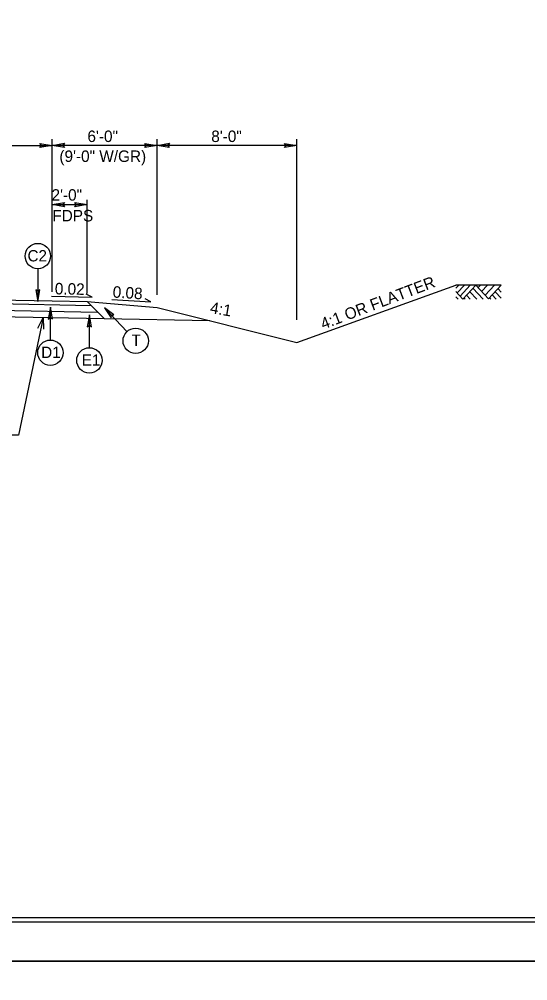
# Model space of a CAD drawing. Extents: x 1901670 to 1902225, y 193498 to 194278.
# Drawn here: x 1902035.7 to 1902064.8, y 193606.9 to 193661.9 of the extents above; entities that cross this region are included whole.
import ezdxf

# ---------------------------------------------------------------- set-up
doc = ezdxf.new("R2010")
doc.units = 0
for name, color, linetype in [('Old_Level_1', 7, 'Continuous'), ('Old_Level_11', 7, 'Continuous'), ('Old_Level_2', 7, 'Continuous'), ('Old_Level_20', 7, 'Continuous'), ('Prop Dimension', 7, 'Continuous'), ('Prop Dimension Text', 7, 'Continuous'), ('Sheet Border Standard 30in CELL', 7, 'Continuous'), ('Sheet Cutting Line CELL', 7, 'Continuous'), ('Sheet Plot Border Inside CELL', 7, 'Continuous'), ('Sheet Plot Border Outside CELL', 7, 'Continuous'), ('Typical Hinge Slope Interstate CELL', 7, 'Continuous'), ('Typical Pavement Slope CELL', 7, 'Continuous'), ('Typical Terminator CELL', 7, 'Continuous')]:
    doc.layers.add(name, color=color, linetype=linetype)

# ---------------------------------------------------------------- blocks, each defined once
blk = doc.blocks.new('TERMINATOR')
at = {"layer": 'Typical Terminator CELL'}
blk.add_lwpolyline([(-0.469, 0.081), (0, 0), (-0.471, -0.083), (-0.411, 0)], close=True, dxfattribs=at)

msp = doc.modelspace()

# ---------------------------------------------------------------- linework, layer by layer
at = {"layer": 'Old_Level_1'}
for p, q in [((1902043.616, 193646.129), (1902043.616, 193655.04)), ((1902060.879, 193646.683), (1902060.709, 193646.5)), ((1902061.113, 193645.886), (1902060.709, 193646.321)), ((1902061.199, 193646.683), (1902060.785, 193646.239)), ((1902061.532, 193646.683), (1902060.952, 193646.06)), ((1902061.854, 193646.682), (1902061.113, 193645.886)), ((1902061.905, 193645.878), (1902061.505, 193646.307)), ((1902062.275, 193645.878), (1902061.689, 193646.506)), ((1902062.586, 193645.896), (1902061.854, 193646.682)), ((1902062.118, 193646.683), (1902061.985, 193646.54)), ((1902062.52, 193646.683), (1902062.187, 193646.324)), ((1902062.918, 193646.683), (1902062.385, 193646.11)), ((1902063.309, 193646.675), (1902062.586, 193645.896)), ((1902063.309, 193645.941), (1902062.967, 193646.307)), ((1902063.309, 193646.274), (1902063.124, 193646.474)), ((1902025.621, 193646.02), (1902037.616, 193645.78)), ((1902025.621, 193645.801), (1902039.84, 193645.517)), ((1902037.587, 193646.051), (1902039.903, 193646.002)), ((1902037.616, 193645.78), (1902039.616, 193645.74)), ((1902039.903, 193646.002), (1902039.57, 193646.169)), ((1902040.583, 193644.773), (1902039.616, 193645.74)), ((1902039.616, 193645.74), (1902043.616, 193645.407)), ((1902041.028, 193645.867), (1902043.263, 193645.722)), ((1902043.263, 193645.722), (1902042.938, 193645.903)), ((1902060.843, 193645.878), (1902060.709, 193646.021)), ((1902061.244, 193645.878), (1902061.175, 193645.952)), ((1902061.539, 193645.878), (1902061.322, 193646.111)), ((1902062.711, 193645.878), (1902062.639, 193645.954)), ((1902063.021, 193645.878), (1902062.794, 193646.121)), ((1902025.621, 193645.437), (1902040.211, 193645.145)), ((1902043.616, 193645.407), (1902051.616, 193643.407)), ((1902025.621, 193645.073), (1902040.583, 193644.773)), ((1902040.583, 193644.773), (1902046.635, 193644.652))]:
    msp.add_line(p, q, dxfattribs=at)
for points in [[(1902063.309, 193646.683), (1902060.709, 193646.683)], [(1902037.096, 193644.834), (1902035.689, 193638.106), (1902030.602, 193638.106)], [(1902036.803, 193644.225), (1902037.096, 193644.834), (1902037.124, 193644.159)]]:
    msp.add_lwpolyline(points, dxfattribs=at)
at = {"layer": 'Old_Level_11'}
for p, q in [((1902036.798, 193647.619), (1902036.798, 193645.745)), ((1902037.515, 193643.543), (1902037.515, 193645.417)), ((1902041.897, 193644.024), (1902040.606, 193645.383)), ((1902039.747, 193643.103), (1902039.747, 193644.977))]:
    msp.add_line(p, q, dxfattribs=at)
for points in [[(1902036.682, 193646.417), (1902036.798, 193645.745), (1902036.917, 193646.42), (1902036.798, 193646.335)], [(1902037.63, 193644.746), (1902037.515, 193645.417), (1902037.395, 193644.742), (1902037.515, 193644.828)], [(1902041.152, 193644.975), (1902040.606, 193645.383), (1902040.984, 193644.811), (1902041.012, 193644.955)], [(1902039.862, 193644.306), (1902039.747, 193644.977), (1902039.627, 193644.302), (1902039.747, 193644.388)]]:
    msp.add_lwpolyline(points, close=True, dxfattribs=at)
for centre in [(1902036.798, 193648.345), (1902042.396, 193643.498), (1902037.515, 193642.818), (1902039.747, 193642.378)]:
    msp.add_circle(centre, 0.725, dxfattribs=at)
at = {"layer": 'Prop Dimension'}
for p, q in [((1902037.616, 193647.349), (1902037.616, 193655.04)), ((1902025.616, 193654.67), (1902037.616, 193654.67))]:
    msp.add_line(p, q, dxfattribs=at)
at = {"layer": 'Prop Dimension Text'}
for p, q in [((1902037.616, 193646.296), (1902037.616, 193655.04)), ((1902051.616, 193644.692), (1902051.616, 193655.04)), ((1902043.616, 193654.67), (1902037.616, 193654.67)), ((1902051.616, 193654.67), (1902043.616, 193654.67)), ((1902037.616, 193651.285), (1902039.616, 193651.285)), ((1902039.616, 193646.207), (1902039.616, 193651.567))]:
    msp.add_line(p, q, dxfattribs=at)
at = {"layer": 'Sheet Border Standard 30in CELL'}
msp.add_lwpolyline([(1902132.544, 193715.514), (1901982.544, 193715.514), (1901982.544, 193610.514), (1902132.544, 193610.514)], close=True, dxfattribs=at)
at = {"layer": 'Sheet Cutting Line CELL'}
for p, q in [((1901965.844, 193608.014), (1902134.244, 193608.014)), ((1902134.244, 193608.014), (1901965.844, 193608.014))]:
    msp.add_line(p, q, dxfattribs=at)
at = {"layer": 'Sheet Plot Border Inside CELL'}
msp.add_lwpolyline([(1902133.794, 193715.769), (1901967.144, 193715.769), (1901967.144, 193610.259), (1902133.794, 193610.259)], close=True, dxfattribs=at)
at = {"layer": 'Sheet Plot Border Outside CELL'}
for points in [[(1902134.244, 193718.014), (1901965.844, 193718.014), (1901965.844, 193608.014), (1902134.244, 193608.014)], [(1902134.244, 193608.014), (1901965.844, 193608.014), (1901965.844, 193498.014), (1902134.244, 193498.014)]]:
    msp.add_lwpolyline(points, close=True, dxfattribs=at)
at = {"layer": 'Typical Pavement Slope CELL'}
msp.add_line((1902051.616, 193643.407), (1902060.709, 193646.683), dxfattribs=at)

# ---------------------------------------------------------------- block references
at = {"layer": 'Prop Dimension', "xscale": 1.5, "yscale": 1.5}
for p in [(1902037.616, 193654.67), (1902043.616, 193654.67), (1902051.616, 193654.67), (1902039.616, 193651.285)]:
    msp.add_blockref('TERMINATOR', p, dxfattribs=at)
at = {"layer": 'Prop Dimension', "xscale": 1.5, "yscale": 1.5, "rotation": 180}
for p in [(1902037.616, 193654.67), (1902043.616, 193654.67), (1902037.616, 193651.285)]:
    msp.add_blockref('TERMINATOR', p, dxfattribs=at)

# ---------------------------------------------------------------- texts
at = {"layer": 'Old_Level_1'}
msp.add_text('4:1 OR FLATTER', height=0.656, rotation=20.8342, dxfattribs=at).set_placement((1902053.126, 193644.138))
at = {"layer": 'Old_Level_2'}
for s, rotation, p in [('0.02', 358.8084, (1902037.764, 193646.158)), ('0.08', 356.2834, (1902041.064, 193645.976))]:
    msp.add_text(s, height=0.656, rotation=rotation, dxfattribs=at).set_placement(p)
at = {"layer": 'Old_Level_20'}
for s, height, p in [('C2', 0.6491, (1902036.209, 193648.038)), ('T', 0.649, (1902042.159, 193643.206)), ('D1', 0.6491, (1902036.993, 193642.514)), ('E1', 0.6491, (1902039.313, 193642.074))]:
    msp.add_text(s, height=height, dxfattribs=at).set_placement(p)
at = {"layer": 'Prop Dimension'}
msp.add_text('8\'-0" ', height=0.656, dxfattribs=at).set_placement((1902046.72, 193654.868))
at = {"layer": 'Prop Dimension Text'}
for s, p in [('6\'-0"', (1902039.635, 193654.868)), ('(9\'-0" W/GR)', (1902038.032, 193653.729)), ('FDPS', (1902037.628, 193650.328))]:
    msp.add_text(s, height=0.656, dxfattribs=at).set_placement(p)
msp.add_text('2\'-0"', height=0.656, rotation=360, dxfattribs=at).set_placement((1902037.581, 193651.514))
at = {"layer": 'Typical Hinge Slope Interstate CELL'}
msp.add_text('4:1', height=0.656, rotation=350.5377, dxfattribs=at).set_placement((1902046.619, 193645.085))

doc.saveas('drawing.dxf')
